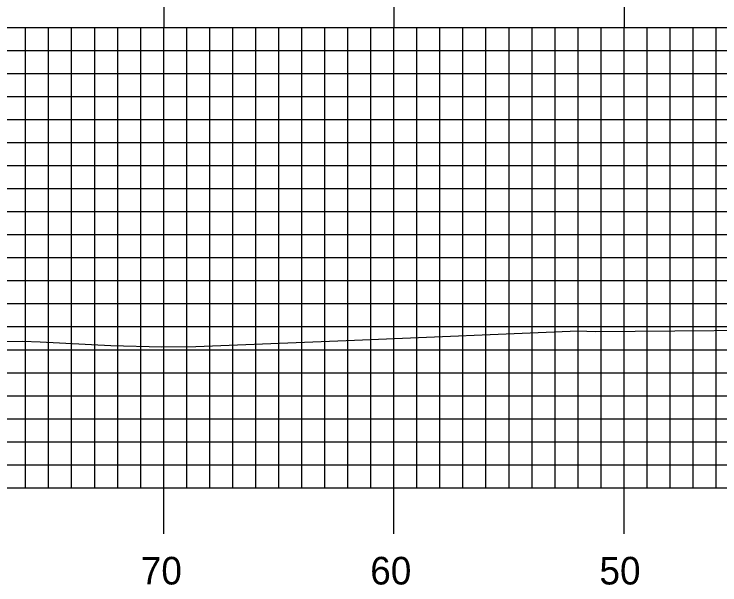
# Model space of a CAD drawing. Extents: x 1825147 to 1825490, y 442591 to 442811.
# Drawn here: x 1825235.86 to 1825266.52, y 442764.45 to 442789.24 of the extents above; entities that cross this region are included whole.
import ezdxf

# ---------------------------------------------------------------- set-up
doc = ezdxf.new("R2010")
doc.units = 0
for name, color, linetype in [('H_V ANNOTATION', 7, 'Continuous'), ('MAJOR', 7, 'Continuous'), ('MINOR', 7, 'Continuous'), ('S_Roadway_Centerline', 7, 'Continuous')]:
    doc.layers.add(name, color=color, linetype=linetype)

msp = doc.modelspace()

# ---------------------------------------------------------------- linework, layer by layer
at = {"layer": 'MAJOR'}
for p, q in [((1825242.361, 442790.669), (1825242.361, 442788.665)), ((1825252.361, 442790.669), (1825252.361, 442788.665)), ((1825262.361, 442790.669), (1825262.361, 442788.665)), ((1825172.361, 442788.665), (1825452.361, 442788.665)), ((1825172.361, 442788.665), (1825452.361, 442788.665)), ((1825242.361, 442768.665), (1825242.361, 442788.665)), ((1825252.361, 442768.665), (1825252.361, 442788.665)), ((1825262.361, 442768.665), (1825262.361, 442788.665)), ((1825172.361, 442783.665), (1825452.361, 442783.665)), ((1825172.361, 442778.665), (1825452.361, 442778.665)), ((1825172.361, 442773.665), (1825452.361, 442773.665)), ((1825172.361, 442768.665), (1825452.361, 442768.665)), ((1825172.361, 442768.665), (1825452.361, 442768.665)), ((1825242.361, 442766.661), (1825242.361, 442768.665)), ((1825252.361, 442766.661), (1825252.361, 442768.665)), ((1825262.361, 442766.661), (1825262.361, 442768.665))]:
    msp.add_line(p, q, dxfattribs=at)
at = {"layer": 'MINOR'}
for p, q in [((1825236.361, 442768.665), (1825236.361, 442788.665)), ((1825237.361, 442768.665), (1825237.361, 442788.665)), ((1825238.361, 442768.665), (1825238.361, 442788.665)), ((1825239.361, 442768.665), (1825239.361, 442788.665)), ((1825240.361, 442768.665), (1825240.361, 442788.665)), ((1825241.361, 442768.665), (1825241.361, 442788.665)), ((1825243.361, 442768.665), (1825243.361, 442788.665)), ((1825244.361, 442768.665), (1825244.361, 442788.665)), ((1825245.361, 442768.665), (1825245.361, 442788.665)), ((1825246.361, 442768.665), (1825246.361, 442788.665)), ((1825247.361, 442768.665), (1825247.361, 442788.665)), ((1825248.361, 442768.665), (1825248.361, 442788.665)), ((1825249.361, 442768.665), (1825249.361, 442788.665)), ((1825250.361, 442768.665), (1825250.361, 442788.665)), ((1825251.361, 442768.665), (1825251.361, 442788.665)), ((1825253.361, 442768.665), (1825253.361, 442788.665)), ((1825254.361, 442768.665), (1825254.361, 442788.665)), ((1825255.361, 442768.665), (1825255.361, 442788.665)), ((1825256.361, 442768.665), (1825256.361, 442788.665)), ((1825257.361, 442768.665), (1825257.361, 442788.665)), ((1825258.361, 442768.665), (1825258.361, 442788.665)), ((1825259.361, 442768.665), (1825259.361, 442788.665)), ((1825260.361, 442768.665), (1825260.361, 442788.665)), ((1825261.361, 442768.665), (1825261.361, 442788.665)), ((1825263.361, 442768.665), (1825263.361, 442788.665)), ((1825264.361, 442768.665), (1825264.361, 442788.665)), ((1825265.361, 442768.665), (1825265.361, 442788.665)), ((1825266.361, 442768.665), (1825266.361, 442788.665)), ((1825172.361, 442787.665), (1825452.361, 442787.665)), ((1825172.361, 442786.665), (1825452.361, 442786.665)), ((1825172.361, 442785.665), (1825452.361, 442785.665)), ((1825172.361, 442784.665), (1825452.361, 442784.665)), ((1825172.361, 442782.665), (1825452.361, 442782.665)), ((1825172.361, 442781.665), (1825452.361, 442781.665)), ((1825172.361, 442780.665), (1825452.361, 442780.665)), ((1825172.361, 442779.665), (1825452.361, 442779.665)), ((1825172.361, 442777.665), (1825452.361, 442777.665)), ((1825172.361, 442776.665), (1825452.361, 442776.665)), ((1825172.361, 442775.665), (1825452.361, 442775.665)), ((1825172.361, 442774.665), (1825452.361, 442774.665)), ((1825172.361, 442772.665), (1825452.361, 442772.665)), ((1825172.361, 442771.665), (1825452.361, 442771.665)), ((1825172.361, 442770.665), (1825452.361, 442770.665)), ((1825172.361, 442769.665), (1825452.361, 442769.665))]:
    msp.add_line(p, q, dxfattribs=at)
at = {"layer": 'S_Roadway_Centerline'}
msp.add_lwpolyline([(1825200.366, 442776.551), (1825204.657, 442776.532), (1825206.293, 442776.503), (1825209.222, 442776.516), (1825210.383, 442776.517), (1825211.047, 442776.362), (1825215.483, 442776.048), (1825221.234, 442775.545), (1825224.236, 442775.276), (1825224.639, 442775.252), (1825226.531, 442775.134), (1825227.676, 442775.072), (1825228.368, 442775.05), (1825233.027, 442775.026), (1825236.221, 442775.027), (1825236.992, 442775.01), (1825240.062, 442774.843), (1825242.28, 442774.783), (1825243.751, 442774.801), (1825250.644, 442775.072), (1825260.365, 442775.484), (1825261.114, 442775.451), (1825271.443, 442775.535)], dxfattribs=at)

# ---------------------------------------------------------------- texts
at = {"layer": 'H_V ANNOTATION'}
for s, p in [('70', (1825241.365, 442764.465)), ('60', (1825251.333, 442764.465)), ('50', (1825261.29, 442764.465))]:
    msp.add_text(s, height=1.2, dxfattribs=at).set_placement(p)

doc.saveas('drawing.dxf')
